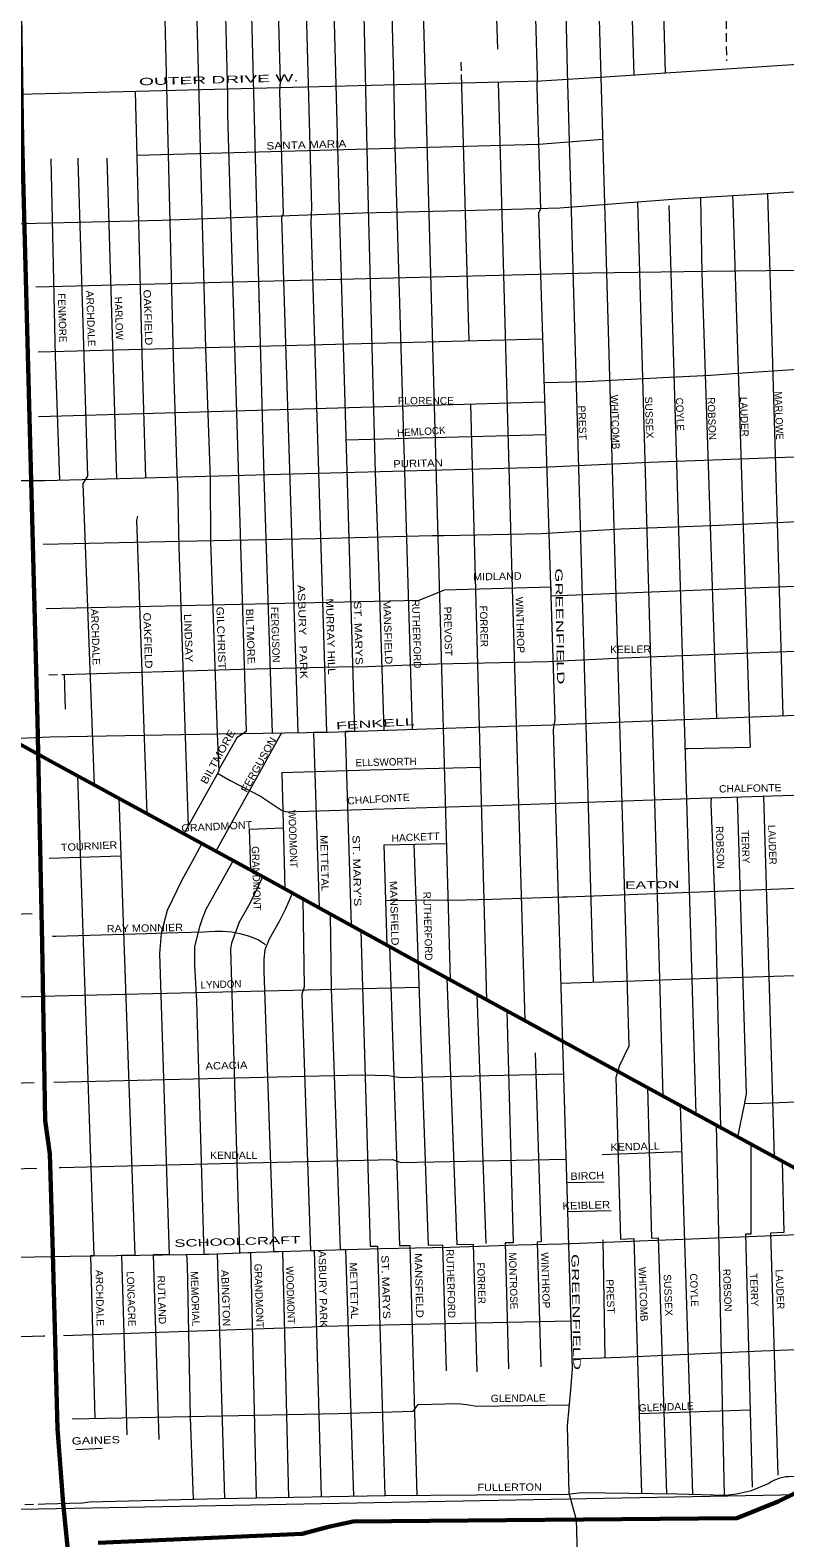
# Model space of a CAD drawing. Extents: x 34705 to 138605, y 34275 to 143551.
# Drawn here: x 53584 to 61287, y 117233 to 132625 of the extents above; entities that cross this region are included whole.
import ezdxf
from ezdxf.enums import TextEntityAlignment as Align

# ---------------------------------------------------------------- set-up
doc = ezdxf.new("R2010")
doc.units = 0
doc.header["$LTSCALE"] = 30
doc.linetypes.add('MEDIUM_DASHED', pattern=[4.5, 3, -1.5])
for name, color, linetype, lineweight in [('1', 7, 'Continuous', 13), ('11', 7, 'Continuous', 13), ('50', 7, 'Continuous', 13), ('51', 7, 'Continuous', 35)]:
    doc.layers.add(name, color=color, linetype=linetype, lineweight=lineweight)

msp = doc.modelspace()

# ---------------------------------------------------------------- linework, layer by layer
at = {"layer": '1'}
for p, q in [((58291.55, 134725.15), (58352.77, 132429.39)), ((59708.86, 133464.8), (59746.84, 132165.25)), ((57984.58, 132171.59), (58061.8, 129452.75)), ((55306.4, 131952.75), (55320.94, 131407.29)), ((54071.24, 131316.49), (54071.56, 131298.6)), ((54368.23, 131318.05), (54463.98, 128045.39)), ((61109.61, 130958.35), (61268.38, 125625.89)), ((55920.96, 129844.52), (55920.12, 129859.15)), ((53665.55, 129339.63), (58815.25, 129472.14)), ((53670.03, 128681.6), (58835.93, 128829.1)), ((56806.95, 128442.15), (58846.65, 128495.84)), ((53929.48, 126047.24), (53942.82, 125693.36)), ((60923.53, 125612.45), (60927.97, 125473.81)), ((60927.98, 125473.45), (60933.36, 125305.55)), ((60267.35, 125291.52), (60298.84, 125292.19)), ((60299.56, 125292.2), (60933.36, 125305.55)), ((55818.96, 124468.84), (56168.63, 124481.64)), ((57193.78, 124309.03), (57832.62, 124321.48)), ((53776.54, 124172.25), (54510.45, 124195.31)), ((59423.26, 121146.16), (60233.81, 121177.5)), ((59059.3, 120860.76), (59442.54, 120868.5)), ((59065.26, 120563.95), (59515.79, 120575.41)), ((59430.33, 120275.31), (59450.82, 119072.96)), ((59799.56, 118502.6), (60933.53, 118538.19)), ((54049.04, 118136.55), (54318.4, 118148.98))]:
    msp.add_line(p, q, dxfattribs=at)
at = {"layer": '1', "linetype": 'MEDIUM_DASHED'}
for p, q in [((57978.69, 132297.79), (57984.57, 132171.93)), ((53773, 126042.63), (53922.89, 126047.21)), ((50021.11, 117463.52), (53735.07, 117578.79))]:
    msp.add_line(p, q, dxfattribs=at)
at = {"layer": '1'}
for points in [[(58482.93, 141303.59), (58501.06, 140739.32), (58563.26, 138855.62), (58577.66, 138625.82), (58716.36, 133469.22), (58725.96, 133349.52), (58759.46, 132146.82), (58754.66, 132041.52), (58792.96, 130796.92), (58773.86, 130758.62), (58940.46, 125579.92), (58922.56, 125484.22), (59115.44, 118962.33), (59098.57, 118742.9), (59064.82, 118377.17), (59080.91, 117690.79), (59156.14, 117419.97)], [(54564.78, 141191.83), (54591.36, 140632.92), (54645.74, 138596.52), (54783.67, 138599.94), (54844.46, 136015.22), (54880.36, 135901.52), (54904.26, 134657.32), (54916.26, 133993.42), (54941.95, 133427.98), (55043.19, 129286.89), (55082.56, 128098.3), (55088.19, 127997.03), (55103.06, 127346.12), (55197.83, 124499.41), (55154.04, 124420.38), (55337.23, 124320.76), (55239.16, 124138.32), (55131.46, 123946.92), (54981.96, 123635.92), (54922.16, 123402.62), (54904.26, 123199.22), (55003.63, 120123.87), (54839.31, 120121.19), (54896.95, 118237.91)], [(54889.8, 141201.1), (54914.26, 140686.72), (54968.6, 138603.14), (55061.09, 138605.94), (55124.76, 136049.42), (55182.16, 135924.92), (55201.36, 134709.12), (55234.86, 134637.32), (55306.29, 131956.82)], [(55207.47, 141210.16), (55234.86, 140634.12), (55289.47, 138610.37), (55358.09, 138611.86), (55431.06, 136041.02), (55450.16, 135939.32), (55483.66, 134709.12), (55512.36, 134637.32), (55545.86, 133343.62), (55565.06, 133319.72), (55593.76, 132089.52), (55598.27, 131963.53)], [(55524.2, 141219.19), (55550.66, 140662.82), (55602.87, 138616.78), (55659.85, 138618.07), (55732.46, 136063.82), (55751.66, 135948.92), (55791.27, 133984.99), (55828.16, 133296.92), (55899.96, 130543.32), (55970.16, 128063.92), (56053.15, 125448.68), (56150.85, 125450.37), (55480.55, 124242.82)], [(55852.16, 141194.12), (55876.06, 140691.52), (55938.26, 138807.82), (55952.66, 138578.02), (55965.63, 137901.03), (56091.36, 133421.42), (56100.96, 133301.72), (56134.46, 132099.02), (56129.66, 131993.72), (56167.96, 130749.12), (56148.86, 130710.82), (56316.45, 125453.22)], [(56154.44, 141237.17), (56180.96, 140679.52), (56243.16, 138795.82), (56257.56, 138566.02), (56339.36, 136106.42), (56315.46, 135968.82), (56454.98, 130811.67), (56449.35, 130665.38), (56608.84, 125458.27), (56475.81, 125455.97), (56533.31, 123667.84), (56646.29, 123600.93), (56657.47, 122841.77), (56748.28, 120175.73), (56801.25, 120177.35), (56883.33, 117658.39)], [(56459.6, 141245.87), (56485.96, 140691.52), (56548.16, 138807.82), (56562.56, 138578.02), (56638.36, 136070.52), (56602.46, 135962.92), (56674.26, 133374.22), (56686.16, 132698.32), (56739.96, 130670.52), (56896.05, 125467.55), (56799.13, 125464.31), (56861.36, 123485.08), (56958.51, 123431.41), (57053.57, 120209.74), (57129.77, 120212.04), (57205.7, 117664.26)], [(56749.23, 141254.13), (56775.76, 140696.32), (56799.66, 139992.62), (56914.46, 136084.12), (56890.56, 136001.52), (56895.36, 135982.42), (56947.96, 134058.12), (56976.66, 133378.32), (57034.32, 130811.67), (57106.26, 128105.82), (57130.16, 127465.72), (57195.07, 125477.54)], [(57350.18, 141271.28), (57378.66, 140672.42), (57388.26, 140011.72), (57431.26, 138716.92), (57451.91, 138008.03), (57421.15, 138008.69), (57474.36, 136098.52), (57507.86, 135997.92), (57871.27, 122928.9), (57837.21, 122947.63), (57938.6, 120227.09), (58104.41, 120232.58), (58141.77, 118928.03)], [(59887.36, 138743.22), (59896.96, 138446.42), (59987.86, 136166.72), (59959.06, 136047.02), (60065.39, 132185.79)], [(57120.4, 138649.23), (57187.26, 136063.82), (57293.05, 132150.77), (57306.86, 131438.52), (57482.08, 125487.13)], [(65163.88, 137331.21), (65305.76, 132788.02), (64749.46, 132412.01), (64626.83, 132338.41), (62738.28, 132301.61), (61417.93, 132272.99), (59451.71, 132146.22), (58797.67, 132105.33), (50401.39, 131888.61), (50311.46, 131843.63), (50205.17, 131778.2), (50123.42, 131716.87), (50074.37, 131655.53), (50021.66, 131579.38)], [(59371.01, 133445.82), (59693.86, 122254.12), (59598.26, 122056.72), (59562.36, 121931.12), (59610.86, 120282.15), (59746.91, 120287.31), (59823.66, 117686.56)], [(59037.76, 133427.09), (59066.22, 132205.63), (59329.66, 122906.03)], [(58361.71, 132094.08), (58502.35, 126928), (58631.74, 122513.85), (58448.8, 122613.73), (58514.33, 120246.17), (58431.31, 120243.42), (58467.71, 118958.32)], [(54657, 131998.45), (54722.58, 129320.65), (54761.08, 128053.43)], [(55598.56, 131963.66), (55598.56, 131869.32), (55598.56, 131831.02), (55598.56, 131759.22), (55609.05, 131412.8)], [(54672.93, 131348.02), (58775.31, 131459.21), (59426.75, 131513.4)], [(53794.34, 131310.42), (53839.51, 129292.52), (53883.41, 128029.67)], [(54071.56, 131298.6), (54168.76, 128072.92), (54120.96, 127995.12), (54237.91, 124920.25), (54068.38, 125012.75), (54232.75, 120111.32), (54199.56, 120110.78), (54243.38, 118451.62)], [(55321.01, 131404.4), (55375.05, 129376.91), (55419.96, 128040.02), (55425.96, 127399.92), (55493.16, 125442.6), (55508.16, 125059.52), (55154.04, 124420.38)], [(55609.11, 131411.13), (55789.26, 125466.32), (55693.56, 125400.52), (55508.16, 125077.52)], [(35186.55, 130231.58), (35458.2, 130231.58), (37489.31, 130321.29), (37869.15, 130321.29), (40074.35, 130374.07), (43172.44, 130363.51), (44385.83, 130374.07), (48329.33, 130516.55), (49305.31, 130558.77), (49933.11, 130564.05), (54929.09, 130685.43), (56976.03, 130759.31), (58131.38, 130785.7), (58991.3, 130812.08), (60184.9, 130901.8), (61393.02, 130975.68), (61503.8, 130980.96), (63404.33, 131007.34), (65002.84, 131017.9), (66400.87, 131039.01), (66997.01, 131039.01), (67635.36, 131075.95), (68722.14, 131123.45), (70126.76, 131153.79)], [(59784.66, 130871.71), (60043.44, 121743.15), (59885.38, 121829.44), (59924.91, 120294.06), (59995.11, 120296.72), (60079.64, 117683.15)], [(60102.95, 130835.61), (60378.54, 121560.17), (60218.1, 121645.06), (60345.83, 117677.53)], [(60424.87, 130916.47), (60438.36, 130142.62), (60589.1, 125599.41)], [(60753.65, 130936.58), (60755.26, 130866.42), (60923.5, 125613.25)], [(53641.83, 130003.8), (59314.43, 130147.14), (60490.89, 130162.97), (61403.57, 130173.53), (62405.93, 130205.19), (64021.58, 130242.13), (64078.52, 130242.13), (64084.72, 130056.96), (64918.43, 130067.98), (65261.34, 130136.59), (66416.7, 130152.42), (66585.53, 130156.09)], [(58829.54, 129027.71), (59255.08, 129038.91), (60105.77, 129081.13), (60527.82, 129102.23), (60807.42, 129123.34), (61472.15, 129165.56), (62458.69, 129207.78), (63846.17, 129255.28), (64157.43, 129271.11), (65926.07, 129313.33), (67028.67, 129334.44), (67166.41, 129336.85)], [(50901.75, 127912.29), (51076.59, 127951.78), (53429.51, 128025.66), (53735.5, 128025.66), (58802.7, 128162.87), (59905.3, 128215.65), (61846.72, 128284.25), (63556.01, 128358.13), (63587.66, 128358.13), (64447.59, 128389.8), (65614.81, 128410.91), (67682.84, 128463.68), (68864.58, 128479.51), (72639.26, 128541.52), (73551.93, 128552.07), (74601.78, 128562.63), (77161.76, 128625.95), (79066.25, 128678.73), (79790.99, 128701.73)], [(58080.1, 128807.52), (58242.34, 122726.08), (58142.38, 122781.02), (58235.13, 120236.92)], [(53715.48, 127376.97), (55113.74, 127408.22), (56506.5, 127434.6), (57688.23, 127466.27), (57809.57, 127466.27), (58801.38, 127487.38), (59613.83, 127534.87), (60543.64, 127566.54), (61788.69, 127624.59), (64475.28, 127730.13), (65008.11, 127735.41), (65678.11, 127756.52), (66727.96, 127772.35), (66849.3, 127777.63), (67856.94, 127788.18), (68320.99, 127808.15)], [(54679.45, 127662.64), (54671.06, 127621.22), (54774.55, 124627.44), (54489.61, 124782.92), (54650.97, 120117.6), (54516.59, 120115.6), (54570.21, 118284.44)], [(53746.66, 126719.47), (57553.51, 126804.5), (57730.85, 126877.77), (57811.8, 126912.48), (58897.55, 126941.67), (58899.05, 126849.77), (61811.54, 126966.47), (63565.65, 127032.03), (65305.29, 127089.87), (66770.26, 127109.15), (68783.62, 127163.14), (68790.68, 127163.43)], [(53923.25, 126047.22), (55737.72, 126102.63), (56859.57, 126129.62), (56932.82, 126125.76), (57734.7, 126156.62), (58869.08, 126179.75), (59632.41, 126218.32), (61566.99, 126292.15)], [(53477.78, 125395.11), (53786.04, 125409.43), (55510.26, 125439.32), (56628.26, 125458.6), (58128.89, 125508.73), (58911.49, 125531.87), (59647.83, 125562.72), (61923.34, 125651.42), (63137.72, 125693.84), (63415.3, 125709.27), (64187.29, 125724.69), (65737.07, 125755.55), (67159.64, 125794.11), (67236.74, 125790.25), (67537.44, 125794.11), (68030.91, 125817.25), (68336.42, 125844.24), (68957.11, 125863.53), (69431.29, 125882.81), (69832.23, 125882.81), (71185.01, 125891.95)], [(55496.93, 125039.26), (55625.92, 124964.98), (55934.33, 124803.01), (56150.22, 124660.32), (56196.48, 124644.89), (58409.36, 124714.31), (60322.48, 124779.87), (61583.13, 124822.29), (61671.8, 124837.72), (64198.86, 124926.41), (64869.66, 124941.84), (66377.03, 124972.69), (66974.59, 124984.26), (69826.45, 125057.53), (74698.43, 125096.1), (74810.23, 125157.8), (77421.15, 125238.78)], [(56153.7, 125045.24), (57056.19, 125072.96), (58179.08, 125100.55)], [(56153.7, 125045.24), (56184.98, 123858.53), (56368.64, 123757.07), (56381.26, 122853.72), (56357.26, 122782.02), (56444.84, 120166.54), (56483.83, 120167.76), (56554.89, 117652.48)], [(60536.18, 124787.06), (60532.56, 124727.52), (60580.36, 123541.72), (60629.34, 121424.12), (60584.52, 121447.75), (60668.43, 117668.96)], [(60801.32, 124795.98), (60891.26, 121765.12), (60867.36, 121639.42), (60804.74, 121327.49), (60938.77, 121254.22), (60940.78, 120334.69), (60886.23, 120332.43), (60954.32, 117751.91)], [(61070.35, 124805.03), (61177.23, 121123.61), (61260.53, 121078.51), (61276.22, 120348.56), (61142.06, 120343.01), (61214.34, 117872.81)], [(55818.96, 124468.84), (55834.06, 124050.58), (55958.48, 123982.92), (55825.16, 123709.12), (55717.46, 123517.72), (55639.76, 123302.42), (55627.76, 123242.62), (55721.21, 120142.96), (55831.84, 120147.44), (55891.68, 117640.54)], [(57193.78, 124309.03), (57225.88, 123283.62), (57253.51, 123268.36), (57352.26, 120216.11), (57457.76, 120217.85), (57529.25, 117666.53)], [(57499.03, 124314.98), (57645.61, 120220.94), (57791.98, 120223.36), (57828.77, 118938.58)], [(55654.99, 124147.96), (55376.66, 123649.32), (55340.76, 123553.62), (55310.86, 123469.92), (55280.96, 123350.22), (55280.96, 123350.22), (55263.06, 123266.52), (55263.06, 123075.12), (55280.96, 122716.22), (55356.68, 120129.61), (55492.05, 120133.83), (55568.65, 117634.73)], [(57212.06, 123738.69), (57829.15, 123746.36), (57894.69, 123742.5), (58291.77, 123754.07), (59020.4, 123777.21), (59066.66, 123777.21), (63131.94, 123931.46), (63768.04, 123950.75), (65506.73, 123997.02), (65649.37, 124000.88), (65857.55, 123815.77), (65911.52, 123792.63), (66081.15, 123800.35), (66536.06, 123811.91), (66817.49, 124124.29), (66909.93, 124155.11)], [(56261.33, 123816.35), (56189.86, 123655.32), (56124.06, 123523.72), (56022.46, 123344.32), (55980.56, 123236.62), (55968.66, 123140.92), (55968.66, 123021.22), (56067.1, 120155.55), (56160.36, 120158.21), (56220.29, 117646.46)], [(46916.68, 119921.92), (52891.98, 120088.09), (53990.71, 120107.37), (55409.41, 120130.51), (55891.31, 120149.79), (57164.48, 120188.36), (57866.12, 120199.93), (58563.91, 120223.06), (59011.11, 120234.63), (60333.44, 120284.77), (62664.85, 120381.18), (62942.42, 120535.44), (65811.63, 120620.28), (69640.78, 120751.4), (73304.16, 120847.81), (73350.43, 120847.81), (73385.12, 120959.64), (73489.21, 121113.9), (73728.23, 121252.73), (77495.7, 123154.91), (77576.66, 123220.47), (77676.9, 123382.44), (77895.97, 123692.55)], [(49852.8, 123476.41), (51645.45, 123541.96), (53604.5, 123605.39)], [(53811.45, 123374.06), (53845.79, 123376.14), (54771.03, 123403.13), (54971.5, 123410.85), (55353.16, 123418.56), (55472.68, 123426.27), (55545.92, 123426.27), (55642.3, 123418.56), (55723.26, 123403.13), (55823.5, 123376.14), (55916.02, 123337.57), (55987.21, 123290.1)], [(58999.16, 122894.01), (59637.23, 122917.22), (59756.74, 122921.08), (60316.7, 122940.36), (61388.44, 122975.07), (62325.25, 123009.78), (63467.34, 123059.91), (64265.36, 123086.91), (64357.88, 123094.62), (66906.16, 123160.18), (67002.54, 123148.61), (68372.09, 123198.74), (68530.15, 123210.31), (70701.57, 123241.16), (74809.89, 123279.88)], [(41099.62, 122454.45), (41458.15, 122462.16), (41766.57, 122469.88), (42005.59, 122473.73), (43281.65, 122493.01), (43412.73, 122485.3), (47717.02, 122597.14), (53834.22, 122766.82), (57551.33, 122855.98)], [(58738.66, 122183.82), (58800.99, 120253.9), (58759.54, 120252.83), (58796.04, 118979.77)], [(53824.79, 121885.15), (56961.73, 121960.83), (57243.16, 121953.11), (57362.67, 121933.83), (59024.51, 121968.87)], [(48569.31, 121745.04), (49749.94, 121768.07), (51041.43, 121806.63), (53623.93, 121880.52)], [(60875.7, 121667.74), (61056.89, 121671.59), (61835.64, 121702.45), (63624.44, 121764.15)], [(41106.93, 120675.49), (41284.67, 120679.54), (41450.44, 120683.39), (41674.04, 120687.25), (41781.99, 120691.1), (41959.32, 120714.24), (42051.85, 120718.1), (43281.65, 120741.24), (50463.84, 120914.78), (51177.05, 120934.06), (51269.57, 120941.77), (53653.08, 121008.37)], [(53881.3, 121014.75), (53892.05, 121015.05), (55665.43, 121057.47), (57281.71, 121096.03), (57366.53, 121065.18), (59049.71, 121100.01)], [(55180.26, 120126.77), (55186.76, 120021.42), (55217.55, 118462.97), (55248.99, 117626.77)], [(53922.79, 119297.84), (56463.46, 119387.63), (56567.55, 119395.34), (59097.58, 119449.5)], [(49308.73, 119152.22), (51188.61, 119210.23), (51323.54, 119225.66), (52696.95, 119264.22), (53718.57, 119295.08), (53733.85, 119295.33)], [(59112.55, 119060.04), (59612.17, 119079.12), (61050.15, 119140.82), (62967.13, 119214.09), (64411.81, 119253.04)], [(54012.31, 118446.86), (56729.45, 118502.94), (57493.97, 118524.67), (57546.1, 118594.19), (57954.42, 118602.88), (58063.02, 118589.85), (58141.21, 118576.81), (59084.43, 118589.72)], [(53735.07, 117578.79), (54116.62, 117590.43), (54188.29, 117599.12), (55521.86, 117633.89), (57211.62, 117664.3), (59068.62, 117677.34), (59211.97, 117694.72), (60189.34, 117681.68), (60680.2, 117668.65), (60793.14, 117681.68), (60946.03, 117716.09)], [(59156.14, 117419.97), (59299.97, 112306.17), (59371.51, 109768.6), (59467.9, 107076.6)]]:
    msp.add_lwpolyline(points, dxfattribs=at)
at = {"layer": '1', "lineweight": 53}
msp.add_lwpolyline([(35051.57, 135383.85), (35124.2, 135323.83), (40544.24, 132389.75), (44352.38, 130313.49), (48721.15, 127927.26), (52359.24, 125955.06), (53781.74, 125169.15), (55156.63, 124418.97), (56043.46, 123936.71), (56442.24, 123716.41), (57585, 123085.31), (70109.98, 116247.42), (80624.23, 110526.89), (82336.58, 109591.28)], dxfattribs=at)
at = {"layer": '1', "linetype": 'MEDIUM_DASHED'}
msp.add_lwpolyline([(60690.78, 132885.71), (60686.12, 132863.92), (60691.07, 132313.04)], dxfattribs=at)
at = {"layer": '11'}
msp.add_line((60946.03, 117716.09), (61128.19, 117791.16), dxfattribs=at)
msp.add_arc((61346, 117468.67), 389.15, 53.31689, 124.03472, dxfattribs=at)
at = {"layer": '50'}
msp.add_lwpolyline([(65035.62, 117740.68), (51320.84, 117480.65), (47627.27, 117368.44), (46180.25, 117354.42), (45362.54, 117350.68), (43373.91, 117338.95), (42070.05, 117290.03), (40546.95, 117248.5)], dxfattribs=at)
at = {"layer": '51', "lineweight": 60}
for points in [[(53247.59, 141475.55), (53367.81, 136119.69), (53437.19, 134090.91), (53460.32, 134053.9), (53501.94, 131503.46), (53659.2, 125572.1), (53705.45, 123295.79), (53737.83, 121494.87), (53784.08, 121152.5), (53816.45, 120138.11), (53862.7, 118347.6), (53920.69, 117583.67), (53996.83, 116839.32), (53996.26, 116300.14), (54017.35, 115245.27), (54103.21, 113517.38), (54126.34, 110285.67), (54140.21, 108707.98), (54144.84, 108035.97), (54101.7, 107394.41), (54140.21, 105981.73), (54195.72, 103679.98), (54256.6, 101226.04)], [(54278.61, 117180.42), (56361.16, 117273.82), (56641.28, 117347.21), (56881.39, 117400.59), (60796.4, 117433.94), (61217.5, 117602.51), (61738.46, 117857.59), (62925.64, 118451.37), (63239.11, 118518.09), (66840.65, 119545.53), (67942.15, 119618.13), (70194.46, 119620.82)]]:
    msp.add_lwpolyline(points, dxfattribs=at)

# ---------------------------------------------------------------- texts
at = {"layer": '11'}
for s, rotation, width, p in [('OUTER DRIVE W.', 1.479, 1.95, (55510.96, 132081.84)), ('SANTA MARIA', 1.712, 1.2, (56404.66, 131417.33)), ('ARCHDALE', 271.911, 1.05, (54164.96, 129677.73)), ('OAKFIELD', 271.911, 1.15, (54749.57, 129690.43)), ('SUSSEX', 271.999, 1.05, (59865.19, 128668.86)), ('MARLOWE', 271.999, 0.95, (61189.79, 128688.39)), ('PREST', 271.999, 1.05, (59182.7, 128616.22)), ('PURITAN', 1.313, 1.15, (57543.86, 128164.97)), ('MIDLAND', 1.037, 1.1, (58353.6, 127011.32)), ('GREENFIELD', 271.036, 1.85, (58952.71, 126537.07)), ('ASBURY   PARK', 271.7, 1.25, (56327.51, 126480.69)), ('WINTHROP', 271.7, 1.05, (58547.79, 126550.53)), ('ARCHDALE', 271.911, 1.05, (54213.27, 126429.46)), ('OAKFIELD', 271.911, 1.15, (54748.24, 126392.32)), ('GILCHRIST', 271.912, 1.2, (55495.54, 126417.18)), ('BILTMORE', 271.911, 1.1, (55795.27, 126435.43)), ('MURRAY HILL', 271.7, 1.15, (56614.39, 126433.34)), ('ST. MARYS', 271.7, 1.2, (56896.9, 126469.01)), ('MANSFIELD', 271.7, 1.15, (57197.82, 126479.18)), ('PREVOST', 271.342, 1.05, (57812.22, 126486.89)), ('LINDSAY', 271.909, 1.15, (55161.94, 126416.58)), ('KEELER', 0.705, 1.05, (59711.59, 126266.72)), ('FENKELL', 3.162, 1.8, (57108.69, 125507.78)), ('BILTMORE', 61.006, 1.2, (55533.72, 125188.92)), ('FERGUSON', 60.855, 1.1, (55948.34, 125107.85)), ('CHALFONTE', 3.368, 1.05, (57141.85, 124738.06)), ('CHALFONTE', 1.208, 1.05, (60935.05, 124848.32)), ('GRANDMONT ', 2.794, 1.1, (55506.37, 124459.1)), ('WOODMONT', 271.855, 0.95, (56228.93, 124367.61)), ('METTETAL', 271.343, 1.1, (56551.66, 124117.89)), ("ST. MARY'S", 271.345, 1.3, (56882.21, 124042.77)), ('HACKETT', 2.684, 1.05, (57519.51, 124348.74)), ('TOURNIER', 2.795, 1.1, (54187.67, 124256.75)), ('MANSFIELD', 271.611, 1.15, (57263.3, 123608.8)), ('EATON', 0.762, 1.6, (59933.69, 123862.22)), ('RAY MONNIER', 1.094, 1.1, (54755.63, 123420.88)), ('ACACIA', 1.581, 1.15, (55588.13, 122017.65)), ('KENDALL', 1.768, 1.1, (59759.81, 121190.53)), ('BIRCH', 1.773, 1.1, (59271.62, 120891.79)), ('KEIBLER', 1.767, 1.15, (59261.7, 120590.67)), ('SCHOOLCRAFT', 1.635, 1.7, (55700.6, 120221.12)), ('ASBURY PARK', 271.199, 1.1, (56535.12, 119772.66)), ('ST. MARYS', 271.611, 1.2, (57177.55, 119793.08)), ('MANSFIELD', 271.611, 1.15, (57516.4, 119808.17)), ('WINTHROP', 271.61, 1.05, (58807.24, 119861.47)), ('GREENFIELD', 271.036, 1.85, (59119.21, 119537.71)), ('ARCHDALE', 271.201, 1.05, (54257.58, 119681.48)), ('RUTLAND', 271.854, 1.05, (54890.63, 119661.82)), ('MEMORIAL', 271.855, 1.05, (55230.81, 119671.81)), ('ABINGTON', 271.854, 1.1, (55543.13, 119679.89)), ('WOODMONT', 271.855, 0.95, (56204.01, 119708.72)), ('METTETAL', 271.608, 1.1, (56852.55, 119754.96)), ('SUSSEX', 272.27, 1.05, (60058.47, 119709.81)), ('PREST', 272.271, 1.05, (59469.36, 119695.79)), ('GLENDALE', 0.784, 1.05, (58567.03, 118622.13)), ('GLENDALE', 2.273, 1.05, (60078.09, 118531.96)), ('GAINES ', 1.855, 1.3, (54274.21, 118192.4)), ('FULLERTON', 0.402, 1.1, (58478.59, 117712.74))]:
    msp.add_text(s, height=75, rotation=rotation, dxfattribs=dict(at, width=width)).set_placement(p, align=Align.CENTER)
for s, rotation, p in [('FENMORE', 271.91, (53874.54, 129686.38)), ('HARLOW', 271.911, (54453.32, 129682.1)), ('WHITCOMB', 271.999, (59517.37, 128622.27)), ('COYLE', 271.999, (60179.61, 128701.53)), ('ROBSON', 271.999, (60504.54, 128657.55)), ('LAUDER', 271.999, (60836.71, 128676.05)), ('HEMLOCK', 3.4, (57578.86, 128489.53)), ('FERGUSON', 271.91, (56049.91, 126452.19)), ('RUTHERFORD', 271.701, (57491.42, 126459.34)), ('FORRER', 271.341, (58178.4, 126537.98)), ('ELLSWORTH', 1.408, (57217.53, 125116.35)), ('ROBSON', 271.77, (60589.22, 124280.72)), ('TERRY', 271.77, (60848.92, 124286.24)), ('LAUDER', 271.768, (61122.89, 124307.25)), ('GRANDMONT', 271.854, (55855.48, 123963.61)), ('RUTHERFORD', 271.61, (57606.22, 123477.27)), ('LYNDON', 1.58, (55532.95, 122846.3)), ('RUTHERFORD', 271.61, (57840.6, 119827.35)), ('MONTROSE', 271.611, (58477.92, 119855.92)), ('LONGACRE', 271.856, (54577.63, 119670.99)), ('GRANDMONT', 271.854, (55882.98, 119702.18)), ('FORRER', 271.61, (58152.05, 119832.01)), ('WHITCOMB', 272.271, (59804.15, 119718.44)), ('COYLE', 272.27, (60324.28, 119760.86)), ('ROBSON', 272.272, (60663.83, 119759.34)), ('TERRY', 272.273, (60936.94, 119762.83)), ('LAUDER', 272.274, (61200.21, 119768.08))]:
    msp.add_text(s, height=75, rotation=rotation, dxfattribs=at).set_placement(p, align=Align.CENTER)
at = {"layer": '11', "width": 1.05}
for s, p in [('FLORENCE', (57624.7, 128804.42)), ('KENDALL', (55661.39, 121101.24))]:
    msp.add_text(s, height=75, dxfattribs=at).set_placement(p, align=Align.CENTER)

doc.saveas('drawing.dxf')
